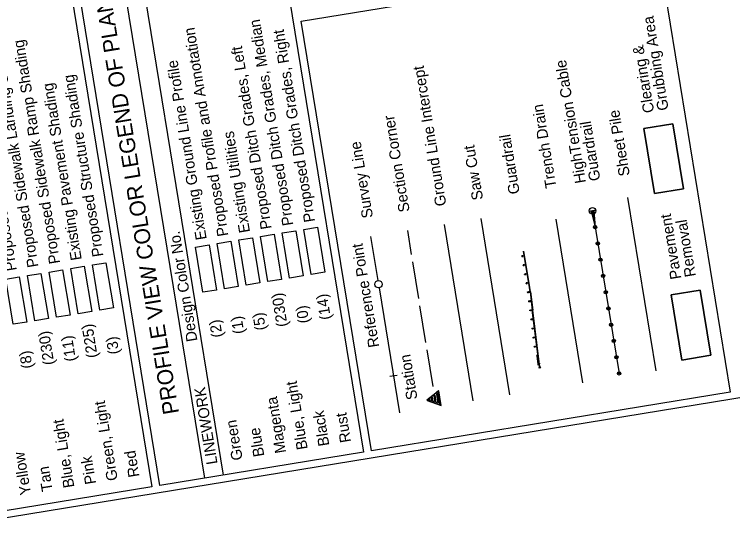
# Model space of a CAD drawing. Extents: x 21481360 to 21488265, y 8074918 to 8087833.
# Drawn here: x 21482042 to 21483023, y 8086342 to 8087066 of the extents above; entities that cross this region are included whole.
import ezdxf

# ---------------------------------------------------------------- set-up
doc = ezdxf.new("R2010")
doc.units = 0
for name, color, linetype in [('Alignment', 7, 'Continuous'), ('Annotation', 7, 'Continuous'), ('brgPreStructureExisting', 7, 'Continuous'), ('Building', 7, 'Continuous'), ('Dimension', 7, 'Continuous'), ('Draft_Plan_Labels', 7, 'Continuous'), ('Drainage', 7, 'Continuous'), ('EXT_C', 7, 'Continuous'), ('EXT_EP', 7, 'Continuous'), ('EXT_SH', 7, 'Continuous'), ('Roadways', 7, 'Continuous'), ('Section Lines', 7, 'Continuous'), ('SheetGridMinor', 7, 'Continuous'), ('SurControl', 7, 'Continuous'), ('SurDrainage', 7, 'Continuous'), ('TC_ChokeStone', 7, 'Continuous'), ('Terrain', 7, 'Continuous'), ('TextAlignment', 7, 'Continuous'), ('TL_SubgradeHinge', 7, 'Continuous'), ('Wall', 7, 'Continuous')]:
    doc.layers.add(name, color=color, linetype=linetype)

msp = doc.modelspace()

# ---------------------------------------------------------------- linework, layer by layer
at = {"layer": 'Alignment'}
msp.add_lwpolyline([(21482417.89, 8086705.94), (21482407.81, 8086767.62), (21482426.31, 8086770.65), (21482436.39, 8086708.96)], close=True, dxfattribs=at)
at = {"layer": 'Annotation'}
for p, q in [((21482528.65, 8086762.69), (21482538.48, 8086702.53)), ((21482540.12, 8086692.5), (21482567.98, 8086522.04)), ((21482564.8, 8086573), (21482554.77, 8086571.36))]:
    msp.add_line(p, q, dxfattribs=at)
msp.add_circle((21482539.3, 8086697.51), 5.08, dxfattribs=at)
at = {"layer": 'brgPreStructureExisting'}
msp.add_line((21482679.06, 8086787.27), (21482718.39, 8086546.62), dxfattribs=at)
at = {"layer": 'Building'}
msp.add_line((21482818.65, 8086563.01), (21482782.16, 8086786.29), dxfattribs=at)
at = {"layer": 'Dimension'}
for p, q in [((21482578.79, 8086770.88), (21482584.14, 8086738.12)), ((21482585.78, 8086728.09), (21482593.97, 8086677.95)), ((21482595.61, 8086667.93), (21482603.81, 8086617.79)), ((21482605.44, 8086607.76), (21482613.64, 8086557.63))]:
    msp.add_line(p, q, dxfattribs=at)
msp.add_lwpolyline([(21482625.16, 8086531.91), (21482621.89, 8086551.96), (21482605.48, 8086538.99), (21482625.16, 8086531.91), (21482622.67, 8086534.59), (21482620.37, 8086548.62), (21482618.53, 8086547.3), (21482620.5, 8086535.26), (21482618.33, 8086535.94), (21482616.69, 8086545.96), (21482614.85, 8086544.63), (21482616.16, 8086536.61), (21482613.99, 8086537.29), (21482613.01, 8086543.3), (21482611.16, 8086541.97), (21482611.82, 8086537.96), (21482609.65, 8086538.64), (21482609.32, 8086540.64), (21482607.48, 8086539.31)], dxfattribs=at)
msp.add_lwpolyline([(21482624.79, 8086531.73), (21482621.51, 8086551.79), (21482605.78, 8086538.92)], close=True, dxfattribs=at)
at = {"layer": 'Draft_Plan_Labels'}
msp.add_lwpolyline([(21482916.66, 8086821.32), (21482902.15, 8086910.14), (21482941.62, 8086916.59), (21482956.14, 8086827.77)], close=True, dxfattribs=at)
at = {"layer": 'Drainage'}
msp.add_line((21482918.92, 8086579.4), (21482880.23, 8086816.14), dxfattribs=at)
at = {"layer": 'EXT_C'}
msp.add_lwpolyline([(21482388.28, 8086701.1), (21482378.2, 8086762.78), (21482396.71, 8086765.81), (21482406.79, 8086704.13)], close=True, dxfattribs=at)
at = {"layer": 'EXT_EP'}
msp.add_lwpolyline([(21482358.68, 8086696.26), (21482348.59, 8086757.94), (21482367.1, 8086760.97), (21482377.18, 8086699.29)], close=True, dxfattribs=at)
at = {"layer": 'Roadways'}
for p, q in [((21482327.61, 8086436.88), (21482134.05, 8087621.17)), ((21482301.95, 8086432.69), (21482108.4, 8087616.97))]:
    msp.add_line(p, q, dxfattribs=at)
msp.add_lwpolyline([(21482956.14, 8086827.77), (21482941.62, 8086916.59), (21482902.15, 8086910.14), (21482916.66, 8086821.32)], close=True, dxfattribs=at)
at = {"layer": 'Section Lines'}
msp.add_lwpolyline([(21482329.07, 8086691.42), (21482318.99, 8086753.11), (21482337.49, 8086756.13), (21482347.57, 8086694.45)], close=True, dxfattribs=at)
at = {"layer": 'SheetGridMinor'}
for points in [[(21482993.29, 8086600.47), (21482978.77, 8086689.29), (21482939.3, 8086682.84), (21482953.81, 8086594.02)], [(21482953.81, 8086594.02), (21482939.3, 8086682.84), (21482978.77, 8086689.29), (21482993.29, 8086600.47)]]:
    msp.add_lwpolyline(points, close=True, dxfattribs=at)
at = {"layer": 'SurControl'}
for p, q in [((21482325.51, 8087652.46), (21482518.82, 8086468.13)), ((21482240.51, 8086422.65), (21482046.96, 8087606.93)), ((21482518.82, 8086468.13), (21482240.51, 8086422.65))]:
    msp.add_line(p, q, dxfattribs=at)
msp.add_lwpolyline([(21481566.94, 8086312.56), (21481373.39, 8087496.85), (21482036.1, 8087605.16), (21482229.65, 8086420.87)], close=True, dxfattribs=at)
for points in [[(21482529.67, 8086469.9), (21482433.79, 8087056.62), (21482924.04, 8087136.74), (21483019.93, 8086550.03), (21482529.67, 8086469.9)], [(21481678.43, 8085630.34), (21481568.45, 8086303.31), (21483540.29, 8086625.57), (21483650.27, 8085952.6), (21481678.43, 8085630.34)]]:
    msp.add_lwpolyline(points, dxfattribs=at)
at = {"layer": 'SurDrainage'}
msp.add_lwpolyline([(21482299.46, 8086686.59), (21482289.38, 8086748.27), (21482307.88, 8086751.29), (21482317.97, 8086689.61)], close=True, dxfattribs=at)
at = {"layer": 'TC_ChokeStone'}
msp.add_lwpolyline([(21482447.5, 8086710.78), (21482437.42, 8086772.46), (21482455.92, 8086775.49), (21482466, 8086713.8)], close=True, dxfattribs=at)
at = {"layer": 'Terrain'}
msp.add_line((21482628.92, 8086779.08), (21482668.25, 8086538.43), dxfattribs=at)
at = {"layer": 'TextAlignment'}
for points in [[(21482158.55, 8086662.14), (21482148.47, 8086723.82), (21482166.97, 8086726.85), (21482177.05, 8086665.16)], [(21482128.94, 8086657.3), (21482118.86, 8086718.98), (21482137.37, 8086722.01), (21482147.45, 8086660.32)]]:
    msp.add_lwpolyline(points, close=True, dxfattribs=at)
at = {"layer": 'TL_SubgradeHinge'}
for p, q in [((21482830, 8086797.38), (21482831.78, 8086797.67)), ((21482830, 8086797.38), (21482835.41, 8086775.46)), ((21482831.78, 8086797.67), (21482833.55, 8086797.96)), ((21482831.78, 8086797.67), (21482868.07, 8086575.62)), ((21482833.55, 8086797.96), (21482835.41, 8086775.46)), ((21482734.97, 8086735.71), (21482734.95, 8086735.71)), ((21482735.08, 8086736.23), (21482736.56, 8086735.46)), ((21482735.24, 8086735.25), (21482736.4, 8086736.45)), ((21482736.4, 8086736.45), (21482738.37, 8086736.77)), ((21482736.56, 8086735.46), (21482736.4, 8086736.45)), ((21482738.53, 8086735.78), (21482736.56, 8086735.46)), ((21482741.48, 8086717.77), (21482737.44, 8086742.45)), ((21482742.01, 8086717.86), (21482737.98, 8086742.53)), ((21482738.37, 8086736.77), (21482738.53, 8086735.78)), ((21482736.98, 8086723.37), (21482736.97, 8086723.37)), ((21482737.1, 8086723.9), (21482738.57, 8086723.13)), ((21482737.26, 8086722.91), (21482738.41, 8086724.11)), ((21482738.41, 8086724.11), (21482740.39, 8086724.44)), ((21482738.57, 8086723.13), (21482738.41, 8086724.11)), ((21482740.55, 8086723.45), (21482738.57, 8086723.13)), ((21482740.39, 8086724.44), (21482740.55, 8086723.45)), ((21482745.51, 8086693.1), (21482741.48, 8086717.77)), ((21482746.04, 8086693.19), (21482742.01, 8086717.86)), ((21482739, 8086711.04), (21482738.99, 8086711.03)), ((21482739.11, 8086711.56), (21482740.59, 8086710.79)), ((21482739.27, 8086710.57), (21482740.43, 8086711.78)), ((21482740.43, 8086711.78), (21482742.4, 8086712.1)), ((21482740.59, 8086710.79), (21482740.43, 8086711.78)), ((21482742.56, 8086711.11), (21482740.59, 8086710.79)), ((21482742.4, 8086712.1), (21482742.56, 8086711.11)), ((21482741.02, 8086698.7), (21482741, 8086698.7)), ((21482741.13, 8086699.22), (21482742.6, 8086698.45)), ((21482741.29, 8086698.24), (21482742.44, 8086699.44)), ((21482742.44, 8086699.44), (21482744.42, 8086699.76)), ((21482742.6, 8086698.45), (21482742.44, 8086699.44)), ((21482744.58, 8086698.78), (21482742.6, 8086698.45)), ((21482744.42, 8086699.76), (21482744.58, 8086698.78)), ((21482743.03, 8086686.39), (21482743.02, 8086686.38)), ((21482743.14, 8086686.91), (21482744.62, 8086686.14)), ((21482743.3, 8086685.92), (21482744.46, 8086687.13)), ((21482746.43, 8086687.45), (21482744.46, 8086687.13)), ((21482744.46, 8086687.13), (21482744.62, 8086686.14)), ((21482744.62, 8086686.14), (21482746.59, 8086686.46)), ((21482746.51, 8086686.95), (21482745.51, 8086693.1)), ((21482747.05, 8086687.02), (21482746.04, 8086693.19)), ((21482746.59, 8086686.46), (21482746.43, 8086687.45)), ((21482746.51, 8086686.95), (21482749.56, 8086662.14)), ((21482747.05, 8086687.02), (21482750.1, 8086662.21)), ((21482744.53, 8086674.17), (21482744.51, 8086674.17)), ((21482744.66, 8086674.69), (21482746.1, 8086673.86)), ((21482744.78, 8086673.7), (21482745.98, 8086674.86)), ((21482747.97, 8086675.1), (21482745.98, 8086674.86)), ((21482745.98, 8086674.86), (21482746.1, 8086673.86)), ((21482746.1, 8086673.86), (21482748.09, 8086674.11)), ((21482748.09, 8086674.11), (21482747.97, 8086675.1)), ((21482746.05, 8086661.77), (21482746.03, 8086661.76)), ((21482746.18, 8086662.29), (21482747.63, 8086661.46)), ((21482746.3, 8086661.29), (21482747.5, 8086662.45)), ((21482758.69, 8086587.7), (21482749.56, 8086662.13)), ((21482759.23, 8086587.76), (21482750.1, 8086662.21)), ((21482747.57, 8086649.36), (21482747.56, 8086649.36)), ((21482747.7, 8086649.88), (21482749.15, 8086649.05)), ((21482747.82, 8086648.89), (21482749.03, 8086650.04)), ((21482749.09, 8086636.95), (21482749.08, 8086636.95)), ((21482749.22, 8086637.47), (21482750.67, 8086636.64)), ((21482749.27, 8086637.06), (21482749.25, 8086637.07)), ((21482749.35, 8086636.48), (21482750.55, 8086637.64)), ((21482750.62, 8086624.55), (21482750.6, 8086624.54)), ((21482750.75, 8086625.07), (21482752.19, 8086624.24)), ((21482750.87, 8086624.07), (21482752.07, 8086625.23)), ((21482752.14, 8086612.14), (21482752.12, 8086612.14)), ((21482752.27, 8086612.66), (21482753.72, 8086611.83)), ((21482752.39, 8086611.67), (21482753.59, 8086612.82)), ((21482757.45, 8086588.15), (21482756.06, 8086599.49)), ((21482757.2, 8086599.9), (21482757.11, 8086600.64)), ((21482758.57, 8086588.91), (21482758.88, 8086586.41)), ((21482759.27, 8086588.43), (21482758.64, 8086588.35)), ((21482759.23, 8086587.76), (21482758.69, 8086587.7)), ((21482759.51, 8086586.48), (21482759.2, 8086588.99))]:
    msp.add_line(p, q, dxfattribs=at)
for points in [[(21482829.24, 8086796.85), (21482829.11, 8086797.64), (21482834.32, 8086798.49), (21482834.45, 8086797.7)], [(21482834.53, 8086774.92), (21482834.4, 8086775.7), (21482836.28, 8086776.01), (21482836.41, 8086775.23)], [(21482838.16, 8086752.71), (21482838.03, 8086753.5), (21482839.91, 8086753.81), (21482840.04, 8086753.02)], [(21482736.56, 8086735.46), (21482736.4, 8086736.45), (21482735.08, 8086736.23), (21482735.24, 8086735.25)], [(21482841.79, 8086730.51), (21482841.66, 8086731.29), (21482843.54, 8086731.6), (21482843.67, 8086730.82)], [(21482738.57, 8086723.13), (21482738.41, 8086724.11), (21482737.1, 8086723.9), (21482737.26, 8086722.91)], [(21482740.59, 8086710.79), (21482740.43, 8086711.78), (21482739.11, 8086711.56), (21482739.27, 8086710.57)], [(21482845.42, 8086708.3), (21482845.29, 8086709.09), (21482847.17, 8086709.39), (21482847.3, 8086708.61)], [(21482742.6, 8086698.45), (21482742.44, 8086699.44), (21482741.13, 8086699.22), (21482741.29, 8086698.24)], [(21482744.46, 8086687.13), (21482744.62, 8086686.14), (21482743.3, 8086685.92), (21482743.14, 8086686.91)], [(21482849.05, 8086686.1), (21482848.92, 8086686.88), (21482850.8, 8086687.19), (21482850.93, 8086686.4)], [(21482745.98, 8086674.86), (21482746.1, 8086673.86), (21482744.78, 8086673.7), (21482744.66, 8086674.69)], [(21482747.5, 8086662.45), (21482747.63, 8086661.46), (21482746.3, 8086661.29), (21482746.18, 8086662.29)], [(21482749.49, 8086662.69), (21482749.61, 8086661.7), (21482747.63, 8086661.46), (21482747.5, 8086662.45)], [(21482852.68, 8086663.89), (21482852.55, 8086664.68), (21482854.43, 8086664.98), (21482854.56, 8086664.2)], [(21482749.03, 8086650.04), (21482749.15, 8086649.05), (21482747.82, 8086648.89), (21482747.7, 8086649.88)], [(21482751.01, 8086650.29), (21482751.13, 8086649.29), (21482749.15, 8086649.05), (21482749.03, 8086650.04)], [(21482750.55, 8086637.64), (21482750.67, 8086636.64), (21482749.35, 8086636.48), (21482749.22, 8086637.47)], [(21482752.54, 8086637.88), (21482752.66, 8086636.89), (21482750.67, 8086636.64), (21482750.55, 8086637.64)], [(21482856.31, 8086641.69), (21482856.18, 8086642.47), (21482858.06, 8086642.78), (21482858.19, 8086641.99)], [(21482752.07, 8086625.23), (21482752.19, 8086624.24), (21482750.87, 8086624.07), (21482750.75, 8086625.07)], [(21482754.06, 8086625.47), (21482754.18, 8086624.48), (21482752.19, 8086624.24), (21482752.07, 8086625.23)], [(21482859.93, 8086619.48), (21482859.81, 8086620.27), (21482861.69, 8086620.57), (21482861.81, 8086619.79)], [(21482753.59, 8086612.82), (21482753.72, 8086611.83), (21482752.39, 8086611.67), (21482752.27, 8086612.66)], [(21482755.58, 8086613.07), (21482755.7, 8086612.07), (21482753.72, 8086611.83), (21482753.59, 8086612.82)], [(21482863.56, 8086597.28), (21482863.44, 8086598.06), (21482865.32, 8086598.37), (21482865.44, 8086597.58)], [(21482758.54, 8086588.91), (21482758.48, 8086588.9), (21482758.42, 8086589.4), (21482758.48, 8086589.41), (21482759.16, 8086589.49), (21482759.22, 8086589.5), (21482759.29, 8086589), (21482759.22, 8086588.99)], [(21482867.19, 8086575.07), (21482867.06, 8086575.86), (21482868.94, 8086576.16), (21482869.07, 8086575.38)]]:
    msp.add_lwpolyline(points, close=True, dxfattribs=at)
for points in [[(21482735.08, 8086735.69), (21482734.97, 8086735.67), (21482734.96, 8086735.75), (21482735.07, 8086735.76)], [(21482735.17, 8086735.67), (21482735.09, 8086735.66), (21482735.06, 8086735.79), (21482735.15, 8086735.81)], [(21482737.1, 8086723.35), (21482736.99, 8086723.33), (21482736.98, 8086723.41), (21482737.08, 8086723.43)], [(21482737.19, 8086723.34), (21482737.1, 8086723.32), (21482737.08, 8086723.46), (21482737.17, 8086723.47)], [(21482739.11, 8086711.02), (21482739.01, 8086711), (21482738.99, 8086711.07), (21482739.1, 8086711.09)], [(21482739.2, 8086711), (21482739.12, 8086710.99), (21482739.1, 8086711.12), (21482739.18, 8086711.13)], [(21482741.13, 8086698.68), (21482741.02, 8086698.66), (21482741.01, 8086698.74), (21482741.12, 8086698.76)], [(21482741.22, 8086698.67), (21482741.13, 8086698.65), (21482741.11, 8086698.78), (21482741.2, 8086698.8)], [(21482743.13, 8086686.44), (21482743.02, 8086686.42), (21482743.04, 8086686.35), (21482743.14, 8086686.36)], [(21482743.21, 8086686.48), (21482743.13, 8086686.47), (21482743.15, 8086686.34), (21482743.23, 8086686.35)], [(21482744.63, 8086674.23), (21482744.52, 8086674.21), (21482744.53, 8086674.14), (21482744.64, 8086674.15)], [(21482744.71, 8086674.26), (21482744.63, 8086674.25), (21482744.64, 8086674.12), (21482744.73, 8086674.13)], [(21482746.15, 8086661.82), (21482746.04, 8086661.81), (21482746.05, 8086661.73), (21482746.16, 8086661.74)], [(21482746.23, 8086661.86), (21482746.15, 8086661.85), (21482746.16, 8086661.71), (21482746.25, 8086661.72)], [(21482747.67, 8086649.41), (21482747.56, 8086649.4), (21482747.57, 8086649.32), (21482747.68, 8086649.33)], [(21482747.75, 8086649.45), (21482747.67, 8086649.44), (21482747.68, 8086649.31), (21482747.77, 8086649.32)], [(21482751.12, 8086649.44), (21482751, 8086650.43)], [(21482749.2, 8086637), (21482749.09, 8086636.99), (21482749.1, 8086636.91), (21482749.2, 8086636.93)], [(21482749.28, 8086637.04), (21482749.19, 8086637.03), (21482749.21, 8086636.9), (21482749.29, 8086636.91)], [(21482750.72, 8086624.6), (21482750.61, 8086624.58), (21482750.62, 8086624.51), (21482750.73, 8086624.52)], [(21482750.8, 8086624.64), (21482750.71, 8086624.63), (21482750.73, 8086624.49), (21482750.82, 8086624.5)], [(21482754.16, 8086624.61), (21482754.04, 8086625.6)], [(21482752.24, 8086612.19), (21482752.13, 8086612.18), (21482752.14, 8086612.1), (21482752.25, 8086612.11)], [(21482752.32, 8086612.23), (21482752.24, 8086612.22), (21482752.25, 8086612.09), (21482752.34, 8086612.1)], [(21482755.69, 8086612.19), (21482755.57, 8086613.18)], [(21482757.1, 8086600.66), (21482755.88, 8086600.51)], [(21482756, 8086599.52), (21482755.88, 8086600.51)], [(21482757.19, 8086599.66), (21482755.91, 8086600.51)], [(21482756.04, 8086599.52), (21482755.91, 8086600.51)], [(21482757.07, 8086600.66), (21482756.04, 8086599.52)], [(21482757.1, 8086599.65), (21482756.04, 8086599.52)], [(21482757.11, 8086599.62), (21482756.05, 8086599.49)], [(21482757.44, 8086588.15), (21482756.05, 8086599.49)], [(21482757.84, 8086588.2), (21482756.45, 8086599.54)], [(21482757.85, 8086588.2), (21482756.46, 8086599.54)], [(21482757.19, 8086599.66), (21482757.07, 8086600.66)], [(21482757.22, 8086599.67), (21482757.1, 8086600.66)], [(21482757.19, 8086599.66), (21482757.1, 8086599.65)], [(21482757.19, 8086599.63), (21482757.11, 8086599.62)], [(21482758.62, 8086588.25), (21482757.4, 8086588.1)], [(21482757.4, 8086588.1), (21482757.5, 8086587.29)], [(21482758.72, 8086587.25), (21482757.43, 8086588.11)], [(21482757.43, 8086588.11), (21482757.53, 8086587.3)], [(21482757.56, 8086587.11), (21482757.43, 8086588.11)], [(21482757.89, 8086588.21), (21482757.44, 8086588.15)], [(21482757.89, 8086588.17), (21482757.44, 8086588.12)], [(21482758.59, 8086588.25), (21482757.56, 8086587.11)], [(21482758.46, 8086588.27), (21482757.89, 8086588.21)], [(21482758.46, 8086588.24), (21482757.89, 8086588.17)], [(21482758.5, 8086588.28), (21482758.46, 8086588.27)], [(21482758.5, 8086588.25), (21482758.46, 8086588.24)], [(21482759.22, 8086588.99), (21482759.16, 8086589.49), (21482758.48, 8086589.41), (21482758.54, 8086588.91)], [(21482758.58, 8086588.29), (21482758.5, 8086588.28)], [(21482758.58, 8086588.26), (21482758.5, 8086588.25)], [(21482758.55, 8086588.91), (21482758.85, 8086586.4), (21482759.53, 8086586.49), (21482759.22, 8086588.99)], [(21482758.59, 8086588.25), (21482758.69, 8086587.44)], [(21482758.72, 8086587.25), (21482758.59, 8086588.25)], [(21482758.62, 8086588.25), (21482758.72, 8086587.44)], [(21482758.72, 8086587.5), (21482758.63, 8086588.18)], [(21482757.5, 8086587.29), (21482757.53, 8086587.3)], [(21482758.72, 8086587.25), (21482757.56, 8086587.11)], [(21482759.08, 8086585.14), (21482758.66, 8086583.53)], [(21482760.96, 8086583.93), (21482758.66, 8086583.53)], [(21482758.66, 8086583.53), (21482758.72, 8086583.2)], [(21482761, 8086583.6), (21482760.94, 8086583.91), (21482758.69, 8086583.51), (21482758.74, 8086583.21)], [(21482758.72, 8086583.2), (21482761.02, 8086583.6)], [(21482758.85, 8086586.4), (21482759.34, 8086583.65)], [(21482759.53, 8086586.49), (21482760.01, 8086583.77)], [(21482759.76, 8086585.23), (21482760.96, 8086583.93)], [(21482760.96, 8086583.93), (21482761.02, 8086583.6)]]:
    msp.add_lwpolyline(points, dxfattribs=at)
for centre, radius in [((21482831.78, 8086797.67), 4.5), ((21482835.41, 8086775.46), 2.25), ((21482839.04, 8086753.26), 2.25), ((21482842.67, 8086731.05), 2.25), ((21482846.29, 8086708.85), 2.25), ((21482849.92, 8086686.64), 2.25), ((21482853.55, 8086664.44), 2.25), ((21482857.18, 8086642.23), 2.25), ((21482860.81, 8086620.03), 2.25), ((21482864.44, 8086597.82), 2.25), ((21482868.07, 8086575.62), 2.25)]:
    msp.add_circle(centre, radius, dxfattribs=at)
for centre, radius, start, end in [((21482756.04, 8086599.53), 0.0417, 186.99661, 276.99661), ((21482757.18, 8086599.67), 0.0417, 276.99661, 6.99661), ((21482757.45, 8086588.11), 0.0417, 96.99661, 186.99661), ((21482757.45, 8086588.11), 0.0103, 96.99661, 186.99661), ((21482758.58, 8086588.25), 0.0417, 6.99661, 96.99661), ((21482758.58, 8086588.25), 0.0103, 6.99661, 96.99661)]:
    msp.add_arc(centre, radius, start, end, dxfattribs=at)
at = {"layer": 'Wall'}
for points in [[(21482099.33, 8086652.46), (21482089.25, 8086714.14), (21482107.76, 8086717.17), (21482117.84, 8086655.49)], [(21482040.12, 8086642.78), (21482030.04, 8086704.47), (21482048.54, 8086707.49), (21482058.63, 8086645.81)], [(21482069.73, 8086647.62), (21482059.65, 8086709.3), (21482078.15, 8086712.33), (21482088.23, 8086650.65)]]:
    msp.add_lwpolyline(points, close=True, dxfattribs=at)

# ---------------------------------------------------------------- texts
at = {"layer": 'EXT_SH'}
for s, height, p in [('PROFILE VIEW COLOR LEGEND OF PLAN AND PROFILE SHEETS', 21.6667, (21482266.86, 8086521.58)), ('Proposed Ditch Grades, Median ', 15, (21482423.12, 8086778.53)), ('Grubbing Area', 15, (21482935.94, 8086935.93)), ('Proposed Sidewalk Landing Shading', 15, (21482074.75, 8086721.59)), ('Proposed Profile and Annotation ', 15, (21482334.3, 8086764.01)), ('Proposed Ditch Grades, Right ', 15, (21482452.73, 8086783.37)), ('Proposed Sidewalk Ramp Shading', 15, (21482104.35, 8086726.43)), ('Proposed Ditch Grades, Left ', 15, (21482393.51, 8086773.69)), ('Clearing & ', 15, (21482916.18, 8086932.7)), ('Existing Ground Line Profile ', 15, (21482304.69, 8086759.17)), ('HighTension Cable ', 15, (21482822.88, 8086836.51)), ('Ground Line Intercept', 15, (21482632.23, 8086805.35)), ('Proposed Structure Shading', 15, (21482163.57, 8086736.11)), ('Existing Pavement Shading', 15, (21482133.96, 8086731.27)), ('Proposed Sidewalk Shading', 15, (21482045.14, 8086716.75)), ('Trench Drain', 15, (21482782.63, 8086829.93)), ('Sheet Pile', 15, (21482882.9, 8086846.32)), ('Section Corner', 15, (21482582.09, 8086797.16)), ('Guardrail', 15, (21482842.65, 8086839.74)), ('Existing Utilities ', 15, (21482363.91, 8086768.85)), ('Guardrail', 15, (21482732.5, 8086821.74)), ('Survey Line', 15, (21482531.96, 8086788.97)), ('Saw Cut', 15, (21482682.36, 8086813.55)), ('Pavement ', 15, (21482953.32, 8086705.4)), ('Removal', 15, (21482973.09, 8086708.63)), ('Design Color No.', 15, (21482292.05, 8086620.31)), ('Reference Point', 15, (21482540.57, 8086612.28)), ('(230) ', 15, (21482415.29, 8086640.46)), ('(14) ', 15, (21482474.5, 8086650.13)), ('(0) ', 15, (21482444.9, 8086645.29)), ('(5) ', 15, (21482385.68, 8086635.62)), ('(2) ', 15, (21482326.47, 8086625.94)), ('(1) ', 15, (21482356.07, 8086630.78)), ('(225) ', 15, (21482155.74, 8086598.04)), ('(230) ', 15, (21482096.52, 8086588.36)), ('(11) ', 15, (21482126.13, 8086593.2)), ('(3) ', 15, (21482185.34, 8086602.88)), ('(8) ', 15, (21482066.91, 8086583.52)), ('Station', 15, (21482592.74, 8086541.03)), ('Blue, Light', 15, (21482442.71, 8086472.68)), ('LINEWORK', 15, (21482319.47, 8086452.54)), ('Green, Light', 15, (21482183.16, 8086430.26)), ('Magenta ', 15, (21482413.1, 8086467.84)), ('Black', 15, (21482472.32, 8086477.52)), ('Rust ', 15, (21482501.92, 8086482.36)), ('Blue, Light', 15, (21482123.94, 8086420.58)), ('Green ', 15, (21482353.89, 8086458.17)), ('Blue', 15, (21482383.49, 8086463)), ('Red', 15, (21482212.76, 8086435.1)), ('Yellow', 15, (21482064.73, 8086410.91)), ('Pink', 15, (21482153.55, 8086425.42)), ('Tan', 15, (21482094.33, 8086415.75))]:
    msp.add_text(s, height=height, rotation=99.28189, dxfattribs=at).set_placement(p)

doc.saveas('drawing.dxf')
